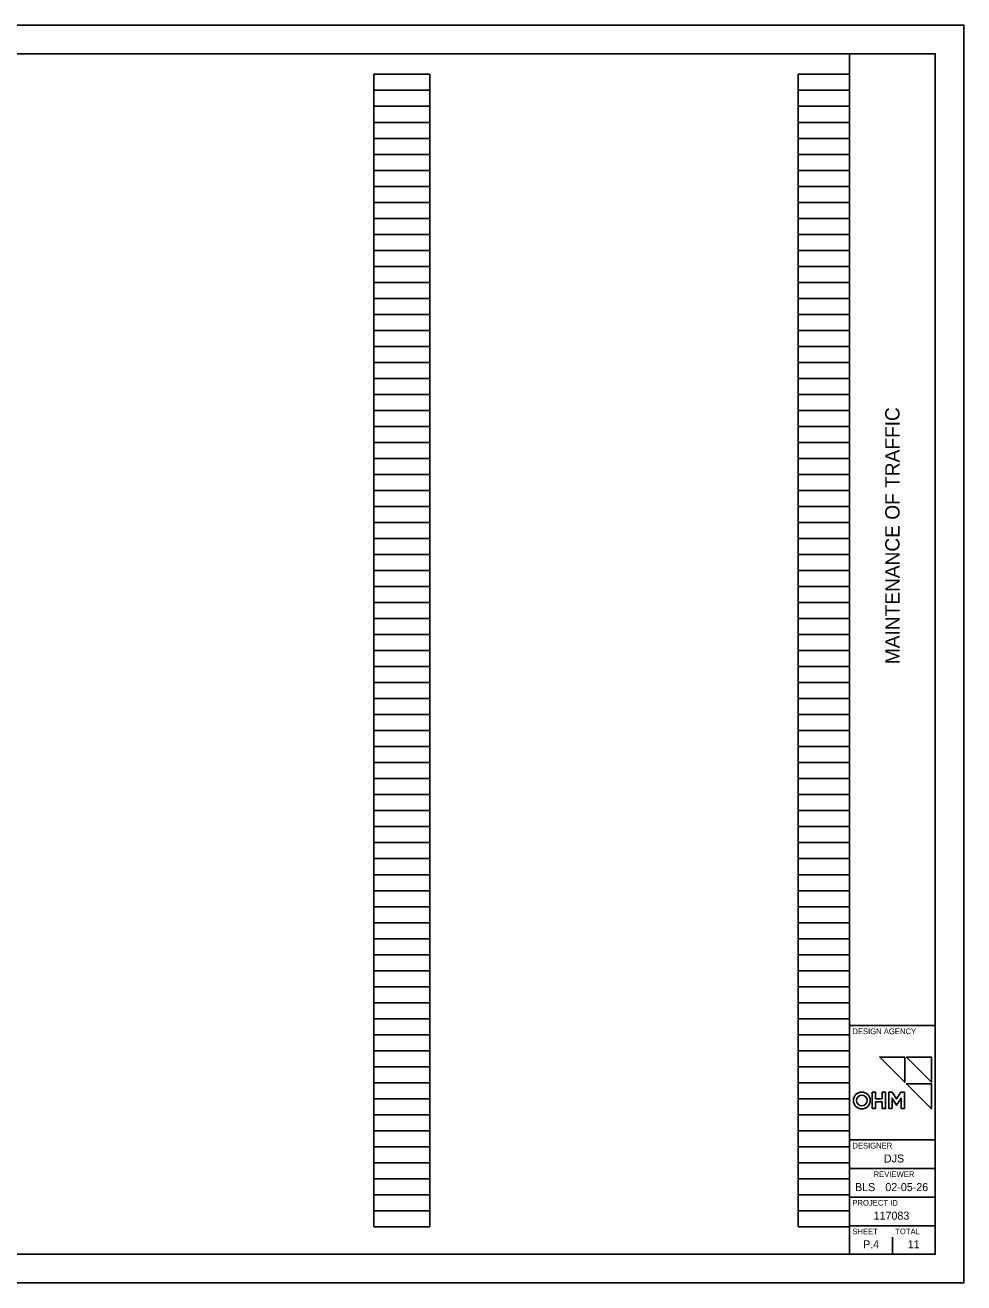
# Model space of a CAD drawing. Extents: x 0 to 34, y 0 to 22.
# Drawn here: x 17.58 to 34, y 0 to 22 of the extents above; entities that cross this region are included whole.
import ezdxf

# ---------------------------------------------------------------- set-up
doc = ezdxf.new("R2010")
doc.units = 0
for name, color, linetype in [('Default', 7, 'Continuous'), ('SH_Border', 7, 'Continuous'), ('SH_Cut_Line', 7, 'Continuous'), ('SH_Data', 7, 'Continuous'), ('TX_P_Misc', 7, 'Continuous')]:
    doc.layers.add(name, color=color, linetype=linetype)

msp = doc.modelspace()

# ---------------------------------------------------------------- linework, layer by layer
at = {"layer": 'Default'}
for points in [[(32.966, 3.948), (32.966, 3.51), (32.53, 3.948)], [(33.433, 3.948), (33.433, 3.51), (32.997, 3.948)], [(32.397, 3.333), (32.457, 3.333), (32.457, 3.22), (32.571, 3.22), (32.571, 3.333), (32.631, 3.333), (32.631, 3.052), (32.571, 3.052), (32.571, 3.166), (32.457, 3.166), (32.457, 3.052), (32.397, 3.052)], [(32.9, 3.335), (32.963, 3.335), (32.963, 3.052), (32.903, 3.052), (32.903, 3.233), (32.824, 3.108), (32.745, 3.233), (32.745, 3.052), (32.685, 3.052), (32.685, 3.335), (32.748, 3.335), (32.824, 3.216)], [(33.433, 3.483), (33.433, 3.045), (32.997, 3.483)]]:
    msp.add_lwpolyline(points, close=True, dxfattribs=at)
at = {"layer": 'SH_Border'}
for p, q in [((32, 0.5), (32, 21.5)), ((32, 4.5), (33.5, 4.5)), ((32, 2.5), (33.5, 2.5)), ((32, 2), (33.5, 2)), ((32, 1.5), (33.5, 1.5)), ((32, 1), (33.5, 1))]:
    msp.add_line(p, q, dxfattribs=at)
msp.add_lwpolyline([(1.5, 21.5), (33.5, 21.5), (33.5, 0.5), (1.5, 0.5)], close=True, dxfattribs=at)
at = {"layer": 'SH_Cut_Line'}
msp.add_lwpolyline([(0, 0), (34, 0), (34, 22), (0, 22)], close=True, dxfattribs=at)
at = {"layer": 'SH_Data'}
for p, q in [((23.68, 0.98), (23.68, 21.14)), ((23.68, 21.14), (24.66, 21.14)), ((24.66, 0.98), (24.66, 21.14)), ((31.1, 0.98), (31.1, 21.14)), ((31.1, 21.14), (32, 21.14)), ((32, 0.98), (32, 21.14)), ((23.68, 20.86), (24.66, 20.86)), ((31.1, 20.86), (32, 20.86)), ((23.68, 20.58), (24.66, 20.58)), ((31.1, 20.58), (32, 20.58)), ((23.68, 20.3), (24.66, 20.3)), ((31.1, 20.3), (32, 20.3)), ((23.68, 20.02), (24.66, 20.02)), ((31.1, 20.02), (32, 20.02)), ((23.68, 19.74), (24.66, 19.74)), ((31.1, 19.74), (32, 19.74)), ((23.68, 19.46), (24.66, 19.46)), ((31.1, 19.46), (32, 19.46)), ((23.68, 19.18), (24.66, 19.18)), ((31.1, 19.18), (32, 19.18)), ((23.68, 18.9), (24.66, 18.9)), ((31.1, 18.9), (32, 18.9)), ((23.68, 18.62), (24.66, 18.62)), ((31.1, 18.62), (32, 18.62)), ((23.68, 18.34), (24.66, 18.34)), ((31.1, 18.34), (32, 18.34)), ((23.68, 18.06), (24.66, 18.06)), ((31.1, 18.06), (32, 18.06)), ((23.68, 17.78), (24.66, 17.78)), ((31.1, 17.78), (32, 17.78)), ((23.68, 17.5), (24.66, 17.5)), ((31.1, 17.5), (32, 17.5)), ((23.68, 17.22), (24.66, 17.22)), ((31.1, 17.22), (32, 17.22)), ((23.68, 16.94), (24.66, 16.94)), ((31.1, 16.94), (32, 16.94)), ((23.68, 16.66), (24.66, 16.66)), ((31.1, 16.66), (32, 16.66)), ((23.68, 16.38), (24.66, 16.38)), ((31.1, 16.38), (32, 16.38)), ((23.68, 16.1), (24.66, 16.1)), ((31.1, 16.1), (32, 16.1)), ((23.68, 15.82), (24.66, 15.82)), ((31.1, 15.82), (32, 15.82)), ((23.68, 15.54), (24.66, 15.54)), ((31.1, 15.54), (32, 15.54)), ((23.68, 15.26), (24.66, 15.26)), ((31.1, 15.26), (32, 15.26)), ((23.68, 14.98), (24.66, 14.98)), ((31.1, 14.98), (32, 14.98)), ((23.68, 14.7), (24.66, 14.7)), ((31.1, 14.7), (32, 14.7)), ((23.68, 14.42), (24.66, 14.42)), ((31.1, 14.42), (32, 14.42)), ((23.68, 14.14), (24.66, 14.14)), ((31.1, 14.14), (32, 14.14)), ((23.68, 13.86), (24.66, 13.86)), ((31.1, 13.86), (32, 13.86)), ((23.68, 13.58), (24.66, 13.58)), ((31.1, 13.58), (32, 13.58)), ((23.68, 13.3), (24.66, 13.3)), ((31.1, 13.3), (32, 13.3)), ((23.68, 13.02), (24.66, 13.02)), ((31.1, 13.02), (32, 13.02)), ((23.68, 12.74), (24.66, 12.74)), ((31.1, 12.74), (32, 12.74)), ((23.68, 12.46), (24.66, 12.46)), ((31.1, 12.46), (32, 12.46)), ((23.68, 12.18), (24.66, 12.18)), ((31.1, 12.18), (32, 12.18)), ((23.68, 11.9), (24.66, 11.9)), ((31.1, 11.9), (32, 11.9)), ((23.68, 11.62), (24.66, 11.62)), ((31.1, 11.62), (32, 11.62)), ((23.68, 11.34), (24.66, 11.34)), ((31.1, 11.34), (32, 11.34)), ((23.68, 11.06), (24.66, 11.06)), ((31.1, 11.06), (32, 11.06)), ((23.68, 10.78), (24.66, 10.78)), ((31.1, 10.78), (32, 10.78)), ((23.68, 10.5), (24.66, 10.5)), ((31.1, 10.5), (32, 10.5)), ((23.68, 10.22), (24.66, 10.22)), ((31.1, 10.22), (32, 10.22)), ((23.68, 9.94), (24.66, 9.94)), ((31.1, 9.94), (32, 9.94)), ((23.68, 9.66), (24.66, 9.66)), ((31.1, 9.66), (32, 9.66)), ((23.68, 9.38), (24.66, 9.38)), ((31.1, 9.38), (32, 9.38)), ((23.68, 9.1), (24.66, 9.1)), ((31.1, 9.1), (32, 9.1)), ((23.68, 8.82), (24.66, 8.82)), ((31.1, 8.82), (32, 8.82)), ((23.68, 8.54), (24.66, 8.54)), ((31.1, 8.54), (32, 8.54)), ((23.68, 8.26), (24.66, 8.26)), ((31.1, 8.26), (32, 8.26)), ((23.68, 7.98), (24.66, 7.98)), ((31.1, 7.98), (32, 7.98)), ((23.68, 7.7), (24.66, 7.7)), ((31.1, 7.7), (32, 7.7)), ((23.68, 7.42), (24.66, 7.42)), ((31.1, 7.42), (32, 7.42)), ((23.68, 7.14), (24.66, 7.14)), ((31.1, 7.14), (32, 7.14)), ((23.68, 6.86), (24.66, 6.86)), ((31.1, 6.86), (32, 6.86)), ((23.68, 6.58), (24.66, 6.58)), ((31.1, 6.58), (32, 6.58)), ((23.68, 6.3), (24.66, 6.3)), ((31.1, 6.3), (32, 6.3)), ((23.68, 6.02), (24.66, 6.02)), ((31.1, 6.02), (32, 6.02)), ((23.68, 5.74), (24.66, 5.74)), ((31.1, 5.74), (32, 5.74)), ((23.68, 5.46), (24.66, 5.46)), ((31.1, 5.46), (32, 5.46)), ((23.68, 5.18), (24.66, 5.18)), ((31.1, 5.18), (32, 5.18)), ((23.68, 4.9), (24.66, 4.9)), ((31.1, 4.9), (32, 4.9)), ((23.68, 4.62), (24.66, 4.62)), ((31.1, 4.62), (32, 4.62)), ((23.68, 4.34), (24.66, 4.34)), ((31.1, 4.34), (32, 4.34)), ((23.68, 4.06), (24.66, 4.06)), ((31.1, 4.06), (32, 4.06)), ((23.68, 3.78), (24.66, 3.78)), ((31.1, 3.78), (32, 3.78)), ((23.68, 3.5), (24.66, 3.5)), ((31.1, 3.5), (32, 3.5)), ((32.75, 3.5), (32.75, 3.5)), ((23.68, 3.22), (24.66, 3.22)), ((31.1, 3.22), (32, 3.22)), ((23.68, 2.94), (24.66, 2.94)), ((31.1, 2.94), (32, 2.94)), ((23.68, 2.66), (24.66, 2.66)), ((31.1, 2.66), (32, 2.66)), ((23.68, 2.38), (24.66, 2.38)), ((31.1, 2.38), (32, 2.38)), ((23.68, 2.1), (24.66, 2.1)), ((31.1, 2.1), (32, 2.1)), ((23.68, 1.82), (24.66, 1.82)), ((31.1, 1.82), (32, 1.82)), ((23.68, 1.54), (24.66, 1.54)), ((31.1, 1.54), (32, 1.54)), ((23.68, 1.26), (24.66, 1.26)), ((31.1, 1.26), (32, 1.26)), ((23.68, 0.98), (24.66, 0.98)), ((31.1, 0.98), (32, 0.98)), ((32.375, 0.675), (32.375, 0.675)), ((32.75, 0.5), (32.75, 0.8))]:
    msp.add_line(p, q, dxfattribs=at)
at = {"layer": 'TX_P_Misc'}
for p, q in [((32.745, 3.052), (32.745, 3.233)), ((32.745, 3.233), (32.824, 3.108)), ((32.824, 3.108), (32.903, 3.233)), ((32.903, 3.233), (32.903, 3.052))]:
    msp.add_line(p, q, dxfattribs=at)
for points in [[(32.53, 3.948), (32.966, 3.51), (32.966, 3.948), (32.53, 3.948)], [(32.997, 3.948), (33.433, 3.51), (33.433, 3.948), (32.997, 3.948)], [(32.824, 3.216), (32.748, 3.335), (32.685, 3.335), (32.685, 3.052), (32.745, 3.052)], [(32.903, 3.052), (32.963, 3.052), (32.963, 3.335), (32.9, 3.335), (32.824, 3.216)], [(32.997, 3.483), (33.433, 3.045), (33.433, 3.483), (32.997, 3.483)]]:
    msp.add_lwpolyline(points, dxfattribs=at)
msp.add_lwpolyline([(32.397, 3.333), (32.457, 3.333), (32.457, 3.22), (32.571, 3.22), (32.571, 3.333), (32.631, 3.333), (32.631, 3.052), (32.571, 3.052), (32.571, 3.166), (32.457, 3.166), (32.457, 3.052), (32.397, 3.052)], close=True, dxfattribs=at)
for radius in [0.148, 0.148, 0.0927, 0.0927]:
    msp.add_circle((32.215, 3.19), radius, dxfattribs=at)

# ---------------------------------------------------------------- texts
at = {"layer": 'SH_Data'}
msp.add_text('MAINTENANCE OF TRAFFIC', height=0.25, rotation=90, dxfattribs=at).set_placement((32.875, 10.822))
for s, height, p in [('DESIGN AGENCY', 0.1, (32.05, 4.35)), ('DESIGNER', 0.1, (32.05, 2.35)), ('DJS', 0.14, (32.602, 2.105)), ('REVIEWER', 0.1, (32.422, 1.85)), ('BLS', 0.14, (32.097, 1.605)), ('02-05-26', 0.14, (32.627, 1.605)), ('PROJECT ID', 0.1, (32.05, 1.35)), ('117083', 0.14, (32.421, 1.105)), ('SHEET', 0.1, (32.05, 0.85)), ('TOTAL', 0.1, (32.8, 0.85)), ('P.4', 0.14, (32.237, 0.605)), ('11', 0.14, (33.019, 0.605))]:
    msp.add_text(s, height=height, dxfattribs=at).set_placement(p)

doc.saveas('drawing.dxf')
